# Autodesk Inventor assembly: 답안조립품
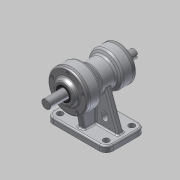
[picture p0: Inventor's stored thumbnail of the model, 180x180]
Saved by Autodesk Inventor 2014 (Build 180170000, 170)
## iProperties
Created: 2015-08
Part Number: 답안조립품
Document SubType Name: Assembly
Designer: net
Author: net
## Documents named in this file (10)
- C:\Users\net\Desktop\450805V1021\답안조립품.iam
- C:\Users\net\Desktop\450805V1021\M4x0.5.ipt
- C:\Users\net\Desktop\450805V1021\뒤커버.ipt
- C:\Users\net\Desktop\450805V1021\베어링 6203.ipt
- C:\Users\net\Desktop\450805V1021\베어링 6205.ipt
- C:\Users\net\Desktop\450805V1021\본체.ipt
- C:\Users\net\Desktop\450805V1021\앞커버.ipt
- C:\Users\net\Desktop\450805V1021\오일실 .ipt
- 오일실 .ipt
- C:\Users\net\Desktop\450805V1021\축.ipt
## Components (10 placed, 1 different names)
1. M4x0.5:1
2. M4x0.5:2
3. M4x0.5:3
4. M4x0.5:4
5. M4x0.5:5
6. M4x0.5:6
7. M4x0.5:7
8. M4x0.5:8
9. M4x0.5:9
10. M4x0.5:10
